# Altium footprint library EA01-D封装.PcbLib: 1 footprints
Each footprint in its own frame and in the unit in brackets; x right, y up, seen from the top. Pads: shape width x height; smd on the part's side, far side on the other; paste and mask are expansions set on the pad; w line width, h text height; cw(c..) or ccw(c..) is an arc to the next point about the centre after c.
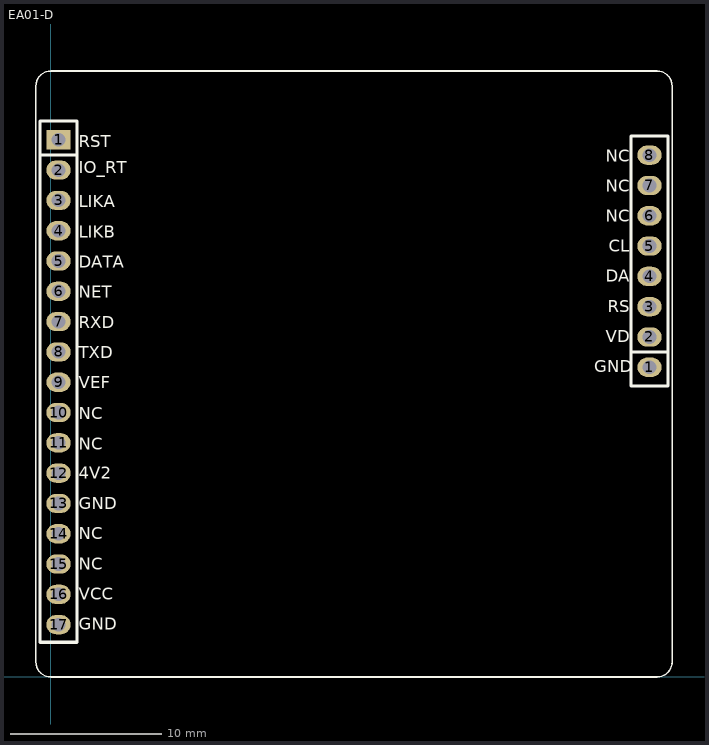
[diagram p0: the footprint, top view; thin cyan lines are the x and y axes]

## EA01-D [mm]
pads (25):
  rect 1.6x1.27 hole 0.9: 1(0.5,35.455)
  oval 1.6x1.27 hole 0.9: 1(39.5,20.442) 2(0.5,33.455) 2(39.5,22.442) 3(0.5,31.455) 3(39.5,24.442) 4(0.5,29.455) 4(39.5,26.442) 5(0.5,27.455) 5(39.5,28.442) 6(0.5,25.455) 6(39.5,30.442) 7(0.5,23.455) 7(39.5,32.442) 8(0.5,21.455) 8(39.5,34.442) 9(0.5,19.455) 10(0.5,17.455) 11(0.5,15.455) 12(0.5,13.455) 13(0.5,11.455) 14(0.5,9.455) 15(0.5,7.455) 16(0.5,5.455) 17(0.5,3.455)
Mid-Layer 2:
  lines w0.254: 0.351,20.991 0.928,20.991
Top Overlay:
  lines w0.1: -1,1 ccw(c0,1) 0,0 40,0 ccw(c40,1) 41,1 41,39 ccw(c40.002,38.998) 40,39.996 0,39.996 ccw(c-0.002,38.998) -1,39 -1,1
  lines w0.203: -0.719,34.439 1.719,34.439 ; 38.281,21.458 40.719,21.458 ; 40.694,35.712 38.281,35.712 38.281,19.198 40.719,19.198 40.719,35.712 ; -0.719,2.295 -0.719,36.7 1.719,36.7 1.719,2.295 -0.719,2.295
  text "GND" at 35.87,20.108 h0.8
  text "VD" at 36.629,22.096 h0.8
  text "RS" at 36.743,24.083 h0.8
  text "DA" at 36.625,26.071 h0.8
  text "CL" at 36.808,28.058 h0.8
  text "NC" at 36.622,30.046 h0.8
  text "NC" at 36.622,32.033 h0.8
  text "NC" at 36.622,34.021 h0.8
  text "GND" at 1.838,3.112 h0.8
  text "VCC" at 1.838,5.103 h0.8
  text "NC" at 1.838,7.094 h0.8
  text "NC" at 1.838,9.086 h0.8
  text "GND" at 1.838,11.077 h0.8
  text "4V2" at 1.838,13.068 h0.8
  text "NC" at 1.838,14.984 h0.8
  text "NC" at 1.838,17.016 h0.8
  text "VEF" at 1.838,19.042 h0.8
  text "TXD" at 1.838,21.033 h0.8
  text "RXD" at 1.838,23.024 h0.8
  text "NET" at 1.838,25.016 h0.8
  text "DATA" at 1.838,27.007 h0.8
  text "LIKB" at 1.838,28.998 h0.8
  text "LIKA" at 1.838,30.989 h0.8
  text "IO_RT" at 1.838,33.247 h0.8
  text "RST" at 1.838,34.972 h0.8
